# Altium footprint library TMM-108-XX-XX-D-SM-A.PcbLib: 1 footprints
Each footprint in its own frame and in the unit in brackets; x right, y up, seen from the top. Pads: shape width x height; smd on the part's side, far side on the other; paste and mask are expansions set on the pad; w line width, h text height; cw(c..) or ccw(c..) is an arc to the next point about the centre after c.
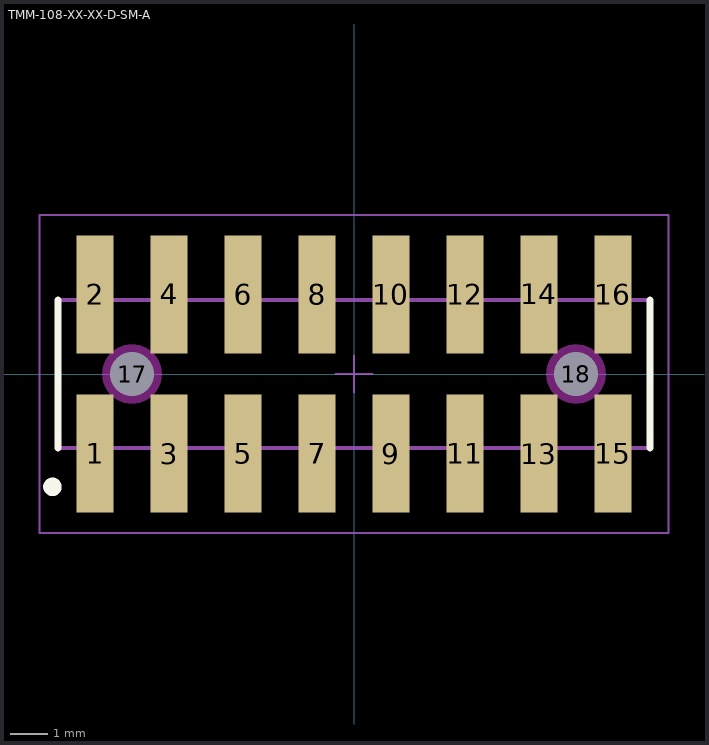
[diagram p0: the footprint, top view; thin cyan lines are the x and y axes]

## TMM-108-XX-XX-D-SM-A [mm] "2.00mm pitch, 16 pin, terminal strip; double row, w/alignment pins, SMT"
height 2.77
pads (18):
  rect 1x3.2 smd mask+0: 1(-7,-2.15) 2(-7,2.15) 3(-5,-2.15) 4(-5,2.15) 5(-3,-2.15) 6(-3,2.15) 7(-1,-2.15) 8(-1,2.15) 9(1,-2.15) 10(1,2.15) 11(3,-2.15) 12(3,2.15) 13(5,-2.15) 14(5,2.15) 15(7,-2.15) 16(7,2.15)
  round 1 hole 1.2 unplated mask+0: 17(-6,0) 18(6,0)
Top Overlay:
  circle w0.25: c-8.15,-3.05 r0.125
  lines w0.2: -8,-2 -8,2 ; 8,-2 8,2
Keep-Out Layer:
  pour cut-out: -5.193,0 -5.221,0.209 -5.301,0.403 -5.429,0.571 -5.597,0.699 -5.791,0.779 -6,0.807 -6.209,0.779 -6.403,0.699 -6.571,0.571 -6.699,0.403 -6.779,0.209 -6.807,0 -6.779,-0.209 -6.699,-0.403 -6.571,-0.571 -6.403,-0.699 -6.209,-0.779 -6,-0.807 -5.791,-0.779 -5.597,-0.699 -5.429,-0.571 -5.301,-0.403 -5.221,-0.209
  pour cut-out: 6.807,0 6.779,0.209 6.699,0.403 6.571,0.571 6.403,0.699 6.209,0.779 6,0.807 5.791,0.779 5.597,0.699 5.429,0.571 5.301,0.403 5.221,0.209 5.193,0 5.221,-0.209 5.301,-0.403 5.429,-0.571 5.597,-0.699 5.791,-0.779 6,-0.807 6.209,-0.779 6.403,-0.699 6.571,-0.571 6.699,-0.403 6.779,-0.209
Mechanical 12:
  lines w0.001: -8,-2 8,-2 8,2 -8,2 -8,-2
Mechanical 13:
  lines w0.1: -8,-2 8,-2 8,2 -8,2 -8,-2
  text ".Designator" at 0,-0.127 h1.52
Mechanical 15:
  lines w0.05: -0.5,0 0.5,0 ; 0,-0.5 0,0.5 ; -8.5,-4.3 8.5,-4.3 8.5,4.3 -8.5,4.3 -8.5,-4.3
